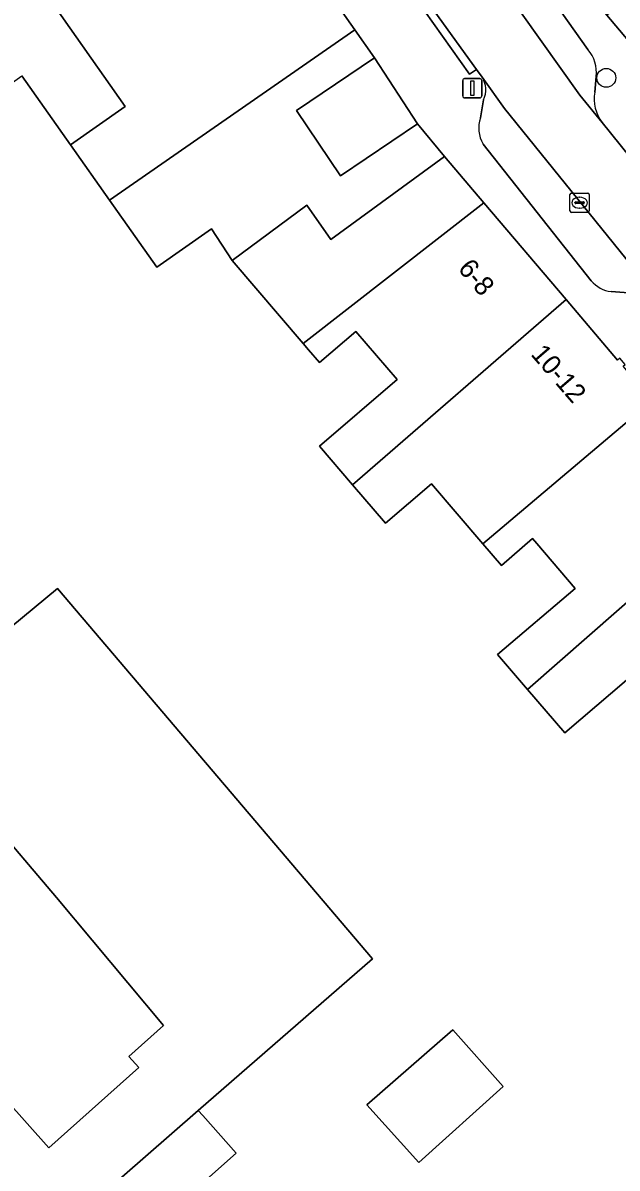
# Model space of a CAD drawing. Extents: x 160663 to 161506, y 382245 to 383291.
# Drawn here: x 160853.7 to 160884.5, y 383116.5 to 383175.8 of the extents above; entities that cross this region are included whole.
import ezdxf

# ---------------------------------------------------------------- set-up
doc = ezdxf.new("R2010")
doc.units = 0
for name, color, linetype in [('IMGEO_Boom', 7, 'Continuous'), ('IMGEO_Erf', 7, 'Continuous'), ('IMGEO_Kolk', 7, 'Continuous'), ('IMGEO_Lichtmast', 7, 'Continuous'), ('IMGEO_Pand', 7, 'Continuous'), ('IMGEO_Pand_nummerreeks', 7, 'Continuous'), ('IMGEO_Parkeervlak_open', 7, 'Continuous'), ('IMGEO_Rijbaan_lokaal_open', 7, 'Continuous'), ('IMGEO_Voetpad_open', 7, 'Continuous')]:
    doc.layers.add(name, color=color, linetype=linetype)

msp = doc.modelspace()

# ---------------------------------------------------------------- linework, layer by layer
at = {"layer": 'IMGEO_Boom'}
msp.add_circle((160883.899, 383172.912), 0.489, dxfattribs=at)
at = {"layer": 'IMGEO_Erf'}
for points in [[(160871.892, 383173.948), (160867.855, 383171.22), (160870.145, 383167.831), (160874.133, 383170.526)], [(160855.448, 383130.467), (160851.849, 383134.678), (160841.544, 383126.254), (160838.066, 383123.41), (160840.66, 383120.426), (160844.049, 383123.372), (160847.23, 383119.601), (160850.542, 383122.549), (160855.036, 383117.501), (160859.707, 383121.66), (160859.189, 383122.242), (160860.986, 383123.842)], [(160875.961, 383123.617), (160878.565, 383120.684), (160874.2, 383116.746), (160871.506, 383119.731)]]:
    msp.add_lwpolyline(points, close=True, dxfattribs=at)
for points in [[(160885.78, 383142.436), (160881.749, 383138.988), (160879.818, 383141.245), (160878.274, 383143.05), (160882.282, 383146.477), (160880.301, 383148.793), (160880.076, 383149.056), (160878.47, 383147.669), (160877.516, 383148.781), (160874.848, 383151.89), (160872.462, 383149.849), (160870.765, 383151.833), (160869.045, 383153.843), (160873.071, 383157.287), (160870.938, 383159.781), (160869.048, 383158.165), (160868.487, 383158.821), (160868.204, 383159.152), (160864.538, 383163.451), (160863.466, 383165.09), (160860.627, 383163.112), (160858.185, 383166.581), (160856.165, 383169.45), (160853.654, 383173.016)], [(160849.437, 383141.466), (160855.494, 383146.477), (160871.792, 383127.293), (160862.78, 383119.438), (160863.018, 383119.171), (160864.744, 383117.232), (160861.516, 383114.358)]]:
    msp.add_lwpolyline(points, dxfattribs=at)
at = {"layer": 'IMGEO_Kolk'}
for p, q in [((160882.018, 383166.021), (160882.018, 383166.873)), ((160882.093, 383166.947), (160882.945, 383166.947)), ((160882.277, 383166.441), (160882.277, 383166.453)), ((160882.32, 383166.49), (160882.718, 383166.49)), ((160882.506, 383166.727), (160882.531, 383166.727)), ((160882.761, 383166.453), (160882.761, 383166.441)), ((160883.019, 383166.873), (160883.019, 383166.021)), ((160882.945, 383165.947), (160882.093, 383165.947)), ((160882.715, 383166.404), (160882.317, 383166.404)), ((160882.529, 383166.167), (160882.504, 383166.167))]:
    msp.add_line(p, q, dxfattribs=at)
for points in [[(160882.018, 383166.021), (160882.018, 383166.873)], [(160882.093, 383166.947), (160882.945, 383166.947)], [(160883.019, 383166.873), (160883.019, 383166.021)], [(160882.945, 383165.947), (160882.093, 383165.947)]]:
    msp.add_lwpolyline(points, dxfattribs=at)
for centre, radius, start, end in [((160882.095, 383166.871), 0.0765, 91.55205, 178.44795), ((160882.095, 383166.871), 0.0765, 91.55205, 178.44795), ((160882.317, 383166.45), 0.0403, 85.87752, 175.75265), ((160882.314, 383166.44), 0.0366, 178.93798, 274.71019), ((160882.718, 383166.447), 0.043, 264.86636, 352.45326), ((160882.722, 383166.452), 0.0386, 1.73085, 96.63898), ((160882.943, 383166.871), 0.0765, 1.55205, 88.44795), ((160882.943, 383166.871), 0.0765, 1.55205, 88.44795), ((160882.095, 383166.023), 0.0765, 181.55205, 268.44795), ((160882.095, 383166.023), 0.0765, 181.55205, 268.44795), ((160882.943, 383166.023), 0.0765, 271.55205, 358.44795), ((160882.943, 383166.023), 0.0765, 271.55205, 358.44795)]:
    msp.add_arc(centre, radius, start, end, dxfattribs=at)
for centre, major_axis, ratio, start_param, end_param in [((160882.505, 383166.447), (-0.387, 0.002), 0.722429, 4.712389, 7.853982), ((160882.53, 383166.447), (-0.39, 0.002), 0.717154, 1.570796, 4.712389)]:
    msp.add_ellipse(centre, major_axis=major_axis, ratio=ratio, start_param=start_param, end_param=end_param, dxfattribs=at)
at = {"layer": 'IMGEO_Lichtmast'}
for p, q in [((160876.465, 383171.976), (160876.465, 383172.776)), ((160876.465, 383172.776), (160876.465, 383171.976)), ((160876.565, 383172.876), (160877.355, 383172.876)), ((160877.355, 383172.876), (160876.565, 383172.876)), ((160877.455, 383172.776), (160877.455, 383171.976)), ((160877.455, 383171.976), (160877.455, 383172.776)), ((160877.355, 383171.876), (160876.565, 383171.876)), ((160876.565, 383171.876), (160877.355, 383171.876))]:
    msp.add_line(p, q, dxfattribs=at)
msp.add_lwpolyline([(160876.885, 383172.751), (160877.035, 383172.751), (160877.035, 383172.001), (160876.885, 383172.001), (160876.885, 383172.751)], dxfattribs=at)
for centre, start, end in [((160876.565, 383172.776), 90, 180), ((160876.565, 383172.776), 90, 180), ((160877.355, 383172.776), 0, 90), ((160877.355, 383172.776), 360, 90), ((160876.565, 383171.976), 180, 270), ((160876.565, 383171.976), 180, 270), ((160877.355, 383171.976), 270, 0), ((160877.355, 383171.976), 270, 0)]:
    msp.add_arc(centre, 0.1, start, end, dxfattribs=at)
at = {"layer": 'IMGEO_Pand'}
for points in [[(160856.165, 383169.45), (160858.185, 383166.581), (160870.875, 383175.395), (160861.86, 383188.217), (160860.186, 383188.504), (160851.374, 383182.272), (160859.003, 383171.423)], [(160895.604, 383179.096), (160900.552, 383182.694), (160900.069, 383183.29), (160898.501, 383185.226), (160897.615, 383184.582), (160892.975, 383181.209), (160888.285, 383177.799), (160887.622, 383178.754), (160883.933, 383176.163), (160889.698, 383169.308), (160898.202, 383176.337)], [(160851.374, 383182.272), (160846.479, 383178.81), (160851.626, 383171.582), (160853.654, 383173.016), (160856.165, 383169.45), (160859.003, 383171.423)], [(160875.522, 383168.848), (160874.133, 383170.526), (160870.145, 383167.831), (160867.855, 383171.22), (160871.892, 383173.948), (160870.875, 383175.395), (160858.185, 383166.581), (160860.627, 383163.112), (160863.466, 383165.09), (160864.538, 383163.451), (160868.402, 383166.312), (160869.648, 383164.54)], [(160864.538, 383163.451), (160868.204, 383159.152), (160877.565, 383166.443), (160875.522, 383168.848), (160869.648, 383164.54), (160868.402, 383166.312)], [(160877.565, 383166.443), (160868.204, 383159.152), (160868.487, 383158.821), (160869.048, 383158.165), (160870.938, 383159.781), (160873.071, 383157.287), (160869.045, 383153.843), (160870.765, 383151.833), (160881.82, 383161.435)], [(160886.307, 383156.228), (160885.706, 383156.931), (160885.813, 383157.023), (160885.51, 383157.378), (160885.378, 383157.265), (160884.767, 383157.979), (160884.871, 383158.068), (160884.595, 383158.39), (160884.486, 383158.297), (160881.82, 383161.435), (160870.765, 383151.833), (160872.462, 383149.849), (160874.848, 383151.89), (160877.516, 383148.781)], [(160890.838, 383150.912), (160888.182, 383154.017), (160888.258, 383154.232), (160888.035, 383154.493), (160887.907, 383154.383), (160887.098, 383155.507), (160886.997, 383155.421), (160886.307, 383156.228), (160877.516, 383148.781), (160878.47, 383147.669), (160880.076, 383149.056), (160880.301, 383148.793), (160882.282, 383146.477), (160878.274, 383143.05), (160879.818, 383141.245)], [(160895.66, 383145.307), (160893.76, 383147.677), (160893.67, 383147.6), (160890.838, 383150.912), (160879.818, 383141.245), (160881.749, 383138.988), (160885.78, 383142.436), (160887.628, 383140.276), (160885.986, 383138.872), (160886.895, 383137.81), (160888.536, 383139.214), (160891.861, 383142.058)], [(160855.494, 383146.477), (160849.437, 383141.466), (160847.865, 383143.697), (160841.468, 383139.204), (160844.287, 383135.367), (160834.654, 383127.38), (160838.066, 383123.41), (160841.544, 383126.254), (160851.849, 383134.678), (160855.448, 383130.467), (160860.986, 383123.842), (160859.189, 383122.242), (160859.707, 383121.66), (160855.036, 383117.501), (160850.542, 383122.549), (160847.23, 383119.601), (160844.049, 383123.372), (160840.66, 383120.426), (160846.678, 383113.478), (160846.774, 383113.543), (160850.763, 383108.963), (160862.78, 383119.438), (160871.792, 383127.293)], [(160875.961, 383123.617), (160871.506, 383119.731), (160874.2, 383116.746), (160878.565, 383120.684)], [(160863.37, 383112.275), (160861.516, 383114.358), (160864.744, 383117.232), (160863.018, 383119.171), (160862.78, 383119.438), (160850.763, 383108.963), (160850.691, 383108.893), (160854.374, 383104.619), (160861.967, 383111.081)]]:
    msp.add_lwpolyline(points, close=True, dxfattribs=at)
at = {"layer": 'IMGEO_Parkeervlak_open'}
for points in [[(160868.41, 383191.859), (160882.534, 383172.02), (160883.679, 383170.601)], [(160882.945, 383174.384), (160877.264, 383182.408), (160871.736, 383190.331)], [(160883.297, 383172.164), (160883.37, 383172.977)], [(160886.809, 383161.208), (160878.623, 383171.333), (160877.474, 383172.957)], [(160877.547, 383171.772), (160877.386, 383170.844)], [(160877.518, 383169.486), (160883.119, 383162.402)], [(160884.15, 383161.847), (160885.051, 383161.775)]]:
    msp.add_lwpolyline(points, dxfattribs=at)
for centre, radius, start, end in [((160881.623, 383173.217), 1.764, 352.18433, 41.43072), ((160876.394, 383172.296), 1.266, 335.56183, 31.48848), ((160885.354, 383171.839), 2.083, 171.01123, 216.45669), ((160878.947, 383170.31), 1.65, 161.12485, 209.97877), ((160884.312, 383163.384), 1.545, 219.44059, 263.97116)]:
    msp.add_arc(centre, radius, start, end, dxfattribs=at)
at = {"layer": 'IMGEO_Rijbaan_lokaal_open'}
msp.add_lwpolyline([(160873.665, 383178.211), (160874.8, 383176.645), (160877.188, 383173.351), (160877.474, 383172.957), (160878.623, 383171.333), (160886.809, 383161.208), (160888.973, 383158.612), (160891.657, 383160.884), (160891.486, 383161.087), (160885.111, 383168.826), (160883.679, 383170.601), (160882.534, 383172.02), (160868.41, 383191.859), (160868.2, 383192.154), (160865.325, 383190.118), (160865.429, 383189.971)], close=True, dxfattribs=at)
at = {"layer": 'IMGEO_Voetpad_open'}
for points in [[(160911.152, 383144.808), (160911.004, 383144.676), (160907.392, 383148.829), (160903.61, 383153.178), (160899.769, 383157.594), (160895.79, 383162.169), (160895.472, 383161.892), (160894.252, 383163.295), (160892.847, 383164.91), (160893.165, 383165.186), (160889.698, 383169.308), (160883.933, 383176.163), (160883.686, 383176.457), (160876.033, 383187.247), (160870.911, 383194.467), (160869.328, 383193.426), (160867.956, 383192.525), (160868.2, 383192.154), (160868.41, 383191.859)], [(160871.736, 383190.331), (160877.264, 383182.408), (160882.945, 383174.384)], [(160861.86, 383188.217), (160870.875, 383175.395), (160871.892, 383173.948), (160874.133, 383170.526), (160875.522, 383168.848), (160877.565, 383166.443), (160881.82, 383161.435), (160884.486, 383158.297)], [(160877.474, 383172.957), (160877.188, 383173.351), (160876.824, 383173.096), (160874.496, 383176.386), (160874.8, 383176.645), (160873.665, 383178.211)], [(160883.37, 383172.977), (160883.297, 383172.164)], [(160877.386, 383170.844), (160877.547, 383171.772)], [(160883.679, 383170.601), (160885.111, 383168.826)], [(160883.119, 383162.402), (160877.518, 383169.486)], [(160885.051, 383161.775), (160884.15, 383161.847)]]:
    msp.add_lwpolyline(points, dxfattribs=at)
msp.add_lwpolyline([(160877.188, 383173.351), (160874.8, 383176.645), (160874.496, 383176.386), (160876.824, 383173.096)], close=True, dxfattribs=at)
for centre, radius, start, end in [((160881.623, 383173.217), 1.764, 352.18433, 41.43072), ((160876.394, 383172.296), 1.266, 335.56183, 31.48848), ((160885.354, 383171.839), 2.083, 171.01123, 216.45669), ((160878.947, 383170.31), 1.65, 161.12485, 209.97877), ((160884.312, 383163.384), 1.545, 219.44059, 263.97116)]:
    msp.add_arc(centre, radius, start, end, dxfattribs=at)

# ---------------------------------------------------------------- texts
at = {"layer": 'IMGEO_Pand_nummerreeks'}
for s, rotation, p in [('6-8', 310.35126, (160876.177, 383163.011)), ('10-12', 310.75428, (160879.948, 383158.582))]:
    msp.add_text(s, height=1, rotation=rotation, dxfattribs=at).set_placement(p)

doc.saveas('drawing.dxf')
